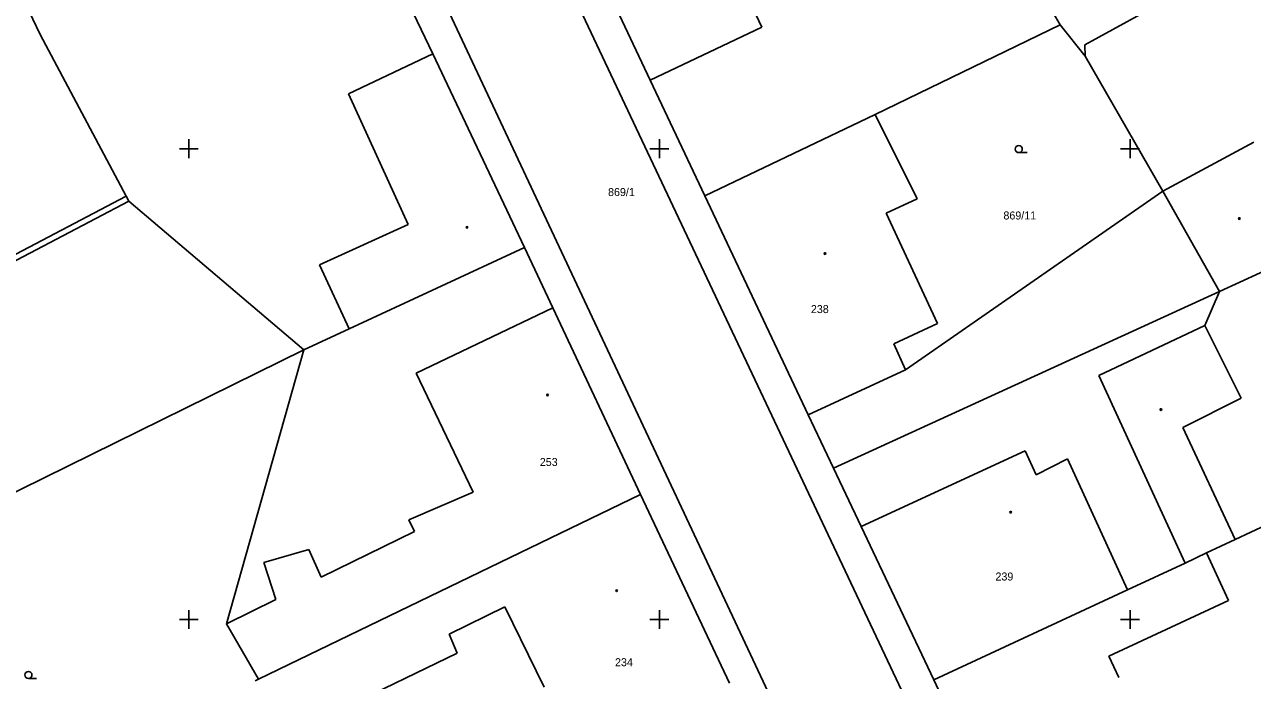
# Model space of a CAD drawing. Extents: x -711081 to -709338, y -1025122 to -1024092.
# Drawn here: x -710758.7 to -710693.5, y -1024978.2 to -1024943.4 of the extents above; entities that cross this region are included whole.
import ezdxf

# ---------------------------------------------------------------- set-up
doc = ezdxf.new("R2010")
doc.units = 0
for name, color, linetype in [('Z_hektometricka_sit', 7, 'Continuous'), ('Z_katastr_cisla_pozemkova', 7, 'Continuous'), ('Z_katastr_cisla_stavebni', 7, 'Continuous'), ('Z_katastr_hranice', 7, 'Continuous'), ('Z_katastr_vnitrni_kresba', 7, 'Continuous'), ('Z_katastr_znacky_budov', 7, 'Continuous'), ('Z_katastr_znacky_kultur', 7, 'Continuous')]:
    doc.layers.add(name, color=color, linetype=linetype)

msp = doc.modelspace()

# ---------------------------------------------------------------- linework, layer by layer
at = {"layer": 'Z_hektometricka_sit'}
for p, q in [((-710750, -1024949.5), (-710750, -1024950.5)), ((-710725, -1024949.5), (-710725, -1024950.5)), ((-710700, -1024949.5), (-710700, -1024950.5)), ((-710750.5, -1024950), (-710749.5, -1024950)), ((-710725.5, -1024950), (-710724.5, -1024950)), ((-710700.5, -1024950), (-710699.5, -1024950)), ((-710750, -1024974.5), (-710750, -1024975.5)), ((-710725, -1024974.5), (-710725, -1024975.5)), ((-710700, -1024974.5), (-710700, -1024975.5)), ((-710750.5, -1024975), (-710749.5, -1024975)), ((-710725.5, -1024975), (-710724.5, -1024975)), ((-710700.5, -1024975), (-710699.5, -1024975))]:
    msp.add_line(p, q, dxfattribs=at)
at = {"layer": 'Z_katastr_hranice'}
for p, q in [((-710717.1, -1024920.2), (-710703.71, -1024943.42)), ((-710734.37, -1024927.6), (-710725.49, -1024946.36)), ((-710760.45, -1024938.53), (-710757.9, -1024943.93)), ((-710737.04, -1024944.96), (-710740.05, -1024938.63)), ((-710757.9, -1024943.93), (-710753.32, -1024952.52)), ((-710713.53, -1024948.18), (-710703.71, -1024943.42)), ((-710703.71, -1024943.42), (-710702.39, -1024945.08)), ((-710732.17, -1024955.24), (-710737.04, -1024944.96)), ((-710702.39, -1024945.08), (-710698.25, -1024952.25)), ((-710725.49, -1024946.36), (-710722.58, -1024952.5)), ((-710714.36, -1024948.58), (-710713.53, -1024948.18)), ((-710711.31, -1024952.66), (-710713.53, -1024948.18)), ((-710722.58, -1024952.5), (-710714.36, -1024948.58)), ((-710698.25, -1024952.25), (-710693.42, -1024949.65)), ((-710698.25, -1024952.25), (-710711.92, -1024961.74)), ((-710753.18, -1024952.78), (-710763.62, -1024958.26)), ((-710753.32, -1024952.52), (-710753.18, -1024952.78)), ((-710753.18, -1024952.78), (-710743.88, -1024960.68)), ((-710722.58, -1024952.5), (-710717.1, -1024964.13)), ((-710712.95, -1024953.42), (-710711.31, -1024952.66)), ((-710710.22, -1024959.28), (-710712.95, -1024953.42)), ((-710732.17, -1024955.24), (-710741.48, -1024959.57)), ((-710730.66, -1024958.45), (-710732.17, -1024955.24)), ((-710695.25, -1024957.58), (-710690.29, -1024955.31)), ((-710715.76, -1024966.96), (-710695.25, -1024957.58)), ((-710696.03, -1024959.39), (-710695.25, -1024957.58)), ((-710726, -1024968.36), (-710730.66, -1024958.45)), ((-710741.48, -1024959.57), (-710743.88, -1024960.68)), ((-710712.55, -1024960.37), (-710710.22, -1024959.28)), ((-710694.09, -1024963.25), (-710696.03, -1024959.39)), ((-710772.17, -1024974.6), (-710743.88, -1024960.68)), ((-710743.88, -1024960.68), (-710747.99, -1024975.23)), ((-710711.92, -1024961.74), (-710712.55, -1024960.37)), ((-710697.19, -1024964.81), (-710694.09, -1024963.25)), ((-710717.1, -1024964.13), (-710715.76, -1024966.96)), ((-710694.42, -1024970.75), (-710697.19, -1024964.81)), ((-710715.76, -1024966.96), (-710714.29, -1024970.07)), ((-710726, -1024968.36), (-710746.3, -1024978.17)), ((-710721.27, -1024978.38), (-710726, -1024968.36)), ((-710714.29, -1024970.07), (-710710.42, -1024978.21)), ((-710692.75, -1024969.97), (-710694.42, -1024970.75)), ((-710695.94, -1024971.46), (-710694.42, -1024970.75)), ((-710700.13, -1024973.42), (-710697.07, -1024972)), ((-710697.07, -1024972), (-710695.94, -1024971.46)), ((-710710.42, -1024978.21), (-710700.13, -1024973.42)), ((-710747.99, -1024975.23), (-710746.3, -1024978.17)), ((-710746.3, -1024978.17), (-710746.48, -1024978.26)), ((-710710.42, -1024978.21), (-710708.963, -1024981.292))]:
    msp.add_line(p, q, dxfattribs=at)
at = {"layer": 'Z_katastr_vnitrni_kresba'}
for p, q in [((-710736.09, -1024928.04), (-710710.637, -1024981.933)), ((-710741.85, -1024930.64), (-710716.679, -1024984.248)), ((-710723.62, -1024934.92), (-710719.56, -1024943.54)), ((-710702.4, -1024944.48), (-710696.33, -1024941.15)), ((-710719.56, -1024943.54), (-710725.49, -1024946.36)), ((-710702.39, -1024945.08), (-710702.4, -1024944.48)), ((-710737.04, -1024944.96), (-710741.52, -1024947.08)), ((-710741.52, -1024947.08), (-710738.35, -1024954.03)), ((-710698.25, -1024952.25), (-710695.25, -1024957.58)), ((-710763.74, -1024957.99), (-710753.32, -1024952.52)), ((-710738.35, -1024954.03), (-710743.05, -1024956.17)), ((-710743.05, -1024956.17), (-710741.48, -1024959.57)), ((-710730.66, -1024958.45), (-710737.92, -1024961.92)), ((-710701.66, -1024962.04), (-710696.03, -1024959.39)), ((-710737.92, -1024961.92), (-710734.9, -1024968.23)), ((-710717.1, -1024964.13), (-710711.92, -1024961.74)), ((-710697.07, -1024972), (-710701.66, -1024962.04)), ((-710714.29, -1024970.07), (-710705.57, -1024966.04)), ((-710705.57, -1024966.04), (-710704.98, -1024967.32)), ((-710704.98, -1024967.32), (-710703.32, -1024966.47)), ((-710703.32, -1024966.47), (-710700.13, -1024973.42)), ((-710734.9, -1024968.23), (-710738.31, -1024969.71)), ((-710738.31, -1024969.71), (-710738.01, -1024970.32)), ((-710738.01, -1024970.32), (-710742.96, -1024972.75)), ((-710743.62, -1024971.29), (-710746.01, -1024971.97)), ((-710742.96, -1024972.75), (-710743.62, -1024971.29)), ((-710746.01, -1024971.97), (-710745.37, -1024973.93)), ((-710694.77, -1024973.99), (-710695.94, -1024971.46)), ((-710745.37, -1024973.93), (-710747.99, -1024975.23)), ((-710701.12, -1024976.95), (-710694.77, -1024973.99)), ((-710736.17, -1024975.77), (-710733.21, -1024974.33)), ((-710733.21, -1024974.33), (-710731.12, -1024978.6)), ((-710735.74, -1024976.79), (-710736.17, -1024975.77)), ((-710745.03, -1024981.27), (-710735.74, -1024976.79)), ((-710700.592, -1024978.085), (-710701.12, -1024976.95))]:
    msp.add_line(p, q, dxfattribs=at)
at = {"layer": 'Z_katastr_znacky_budov'}
for centre in [(-710694.192, -1024953.71), (-710735.222, -1024954.18), (-710716.202, -1024955.57), (-710730.942, -1024963.08), (-710698.362, -1024963.85), (-710706.342, -1024969.3), (-710727.272, -1024973.47)]:
    msp.add_circle(centre, 0.0437, dxfattribs=at)
at = {"layer": 'Z_katastr_znacky_kultur'}
for p, q in [((-710705.908, -1024950.21), (-710705.471, -1024950.21)), ((-710758.518, -1024978.13), (-710758.081, -1024978.13))]:
    msp.add_line(p, q, dxfattribs=at)
for centre in [(-710705.908, -1024950.022), (-710758.518, -1024977.942)]:
    msp.add_circle(centre, 0.187, dxfattribs=at)

# ---------------------------------------------------------------- texts
at = {"layer": 'Z_katastr_cisla_pozemkova'}
for s, p in [('869/1', (-710727.728, -1024952.516)), ('869/11', (-710706.725, -1024953.76))]:
    msp.add_text(s, height=0.425, dxfattribs=at).set_placement(p)
at = {"layer": 'Z_katastr_cisla_stavebni'}
for s, p in [('238', (-710716.953, -1024958.73)), ('253', (-710731.353, -1024966.85)), ('239', (-710707.148, -1024972.929)), ('234', (-710727.358, -1024977.48))]:
    msp.add_text(s, height=0.425, dxfattribs=at).set_placement(p)

doc.saveas('drawing.dxf')
